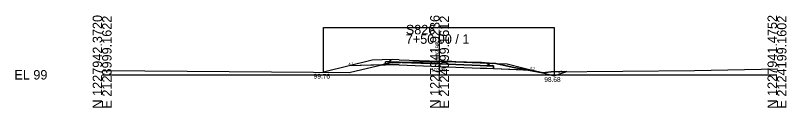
# Model space of a CAD drawing. Extents: x 2118382 to 2118616, y 1213030 to 1222057.
# Drawn here: x 2118381.9 to 2118610.4, y 1218030.1 to 1218057.3 of the extents above; entities that cross this region are included whole.
import ezdxf

# ---------------------------------------------------------------- set-up
doc = ezdxf.new("R2010")
doc.units = 0
for name, color, linetype in [('XS_CELL', 7, 'Continuous'), ('XS_M_DITCH', 7, 'Continuous'), ('XS_M_SHAPES_EARTHWORK', 7, 'Continuous'), ('XS_P_FINISHED_GRADE', 7, 'Continuous'), ('XS_P_FINISHED_GRADE_ELEV_TX', 7, 'Continuous'), ('XS_P_SUBGRADE_GRANULAR', 7, 'Continuous'), ('XS_P_SUBGRADE_PAVEMENT', 7, 'Continuous'), ('XS_P_TX_DCH', 7, 'Continuous'), ('XS_P_TX_FS_BS', 7, 'Continuous'), ('XS_X_GROUND', 7, 'Continuous'), ('XS_X_GROUND_TX', 7, 'Continuous')]:
    doc.layers.add(name, color=color, linetype=linetype)

msp = doc.modelspace()

# ---------------------------------------------------------------- linework, layer by layer
at = {"layer": 'XS_CELL'}
for p, q in [((2118507.6, 1218039.8), (2118507.6, 1218051.76)), ((2118407.6, 1218039.8), (2118507.6, 1218039.8)), ((2118507.6, 1218039.8), (2118607.6, 1218039.8))]:
    msp.add_line(p, q, dxfattribs=at)
at = {"layer": 'XS_M_DITCH'}
for p, q in [((2118473.2, 1218040.56), (2118473.2, 1218053.78)), ((2118473.2, 1218053.78), (2118541.6, 1218053.78)), ((2118541.6, 1218053.78), (2118541.6, 1218039.49))]:
    msp.add_line(p, q, dxfattribs=at)
at = {"layer": 'XS_M_SHAPES_EARTHWORK'}
for p, q in [((2118480.78, 1218042.45), (2118473.2, 1218040.56)), ((2118490.47, 1218042.74), (2118480.78, 1218042.45)), ((2118487.88, 1218042.15), (2118490.47, 1218042.74)), ((2118491.6, 1218043.01), (2118490.47, 1218042.74)), ((2118490.47, 1218042.74), (2118491.6, 1218042.78)), ((2118493.41, 1218043.43), (2118491.6, 1218043.01)), ((2118491.6, 1218043.01), (2118491.6, 1218042.78)), ((2118491.6, 1218042.78), (2118491.6, 1218043.01)), ((2118491.6, 1218042.78), (2118493.6, 1218042.84)), ((2118493.8, 1218043.44), (2118493.41, 1218043.43)), ((2118493.6, 1218042.84), (2118495.6, 1218042.76)), ((2118496.05, 1218043.46), (2118493.8, 1218043.44)), ((2118495.6, 1218042.76), (2118507.6, 1218042.28)), ((2118496.49, 1218043.47), (2118496.05, 1218043.46)), ((2118506.07, 1218043.74), (2118496.49, 1218043.47)), ((2118496.49, 1218043.47), (2118507.6, 1218043.03)), ((2118507.6, 1218043.03), (2118496.49, 1218043.47)), ((2118507.6, 1218043.78), (2118506.07, 1218043.74)), ((2118511.24, 1218043.68), (2118507.6, 1218043.78)), ((2118507.6, 1218043.78), (2118519.6, 1218043.3)), ((2118519.6, 1218043.3), (2118507.6, 1218043.78)), ((2118507.6, 1218043.03), (2118519.6, 1218042.55)), ((2118519.6, 1218042.55), (2118507.6, 1218043.03)), ((2118507.6, 1218042.28), (2118519.6, 1218041.8)), ((2118512.16, 1218043.65), (2118511.24, 1218043.68)), ((2118519.08, 1218043.44), (2118512.16, 1218043.65)), ((2118520.05, 1218043.39), (2118519.08, 1218043.44)), ((2118519.6, 1218043.3), (2118521.6, 1218043.23)), ((2118521.6, 1218043.23), (2118519.6, 1218043.3)), ((2118519.6, 1218042.55), (2118521.6, 1218042.48)), ((2118521.6, 1218042.48), (2118519.6, 1218042.55)), ((2118523.35, 1218043.16), (2118520.05, 1218043.39)), ((2118521.6, 1218043.23), (2118522.28, 1218042.74)), ((2118523.35, 1218043.16), (2118521.6, 1218043.23)), ((2118521.6, 1218043.23), (2118523.35, 1218043.16)), ((2118522.28, 1218042.74), (2118521.6, 1218043.23)), ((2118521.6, 1218042.48), (2118522.45, 1218042.44)), ((2118522.45, 1218042.44), (2118521.6, 1218042.48)), ((2118522.28, 1218042.74), (2118522.45, 1218042.44)), ((2118522.45, 1218042.44), (2118522.28, 1218042.74)), ((2118522.45, 1218042.44), (2118523.6, 1218042.4)), ((2118523.6, 1218042.4), (2118522.45, 1218042.44)), ((2118524.3, 1218043.09), (2118523.35, 1218043.16)), ((2118523.6, 1218042.4), (2118523.6, 1218041.65)), ((2118523.6, 1218041.65), (2118523.6, 1218042.4)), ((2118529.16, 1218042.09), (2118524.3, 1218043.09)), ((2118473.2, 1218040.56), (2118480.83, 1218040.5)), ((2118480.83, 1218040.5), (2118487.88, 1218042.15)), ((2118519.6, 1218041.8), (2118521.6, 1218041.73)), ((2118521.6, 1218041.73), (2118523.6, 1218041.65)), ((2118523.6, 1218041.65), (2118533.4, 1218041.25)), ((2118533.4, 1218041.25), (2118529.16, 1218042.09)), ((2118534.75, 1218041.2), (2118533.4, 1218041.25)), ((2118533.4, 1218041.25), (2118538.07, 1218040.33)), ((2118538.18, 1218040.34), (2118534.75, 1218041.2)), ((2118538.07, 1218040.33), (2118538.18, 1218040.34)), ((2118540.63, 1218040.69), (2118538.18, 1218040.34)), ((2118538.18, 1218040.34), (2118541.6, 1218039.49)), ((2118545.36, 1218040.74), (2118540.63, 1218040.69)), ((2118541.6, 1218039.49), (2118545.36, 1218040.74))]:
    msp.add_line(p, q, dxfattribs=at)
at = {"layer": 'XS_P_FINISHED_GRADE'}
for p, q in [((2118487.6, 1218044.16), (2118473.2, 1218040.56)), ((2118493.6, 1218044.34), (2118487.6, 1218044.16)), ((2118495.6, 1218044.26), (2118493.6, 1218044.34)), ((2118495.6, 1218044.26), (2118507.6, 1218043.78)), ((2118507.6, 1218043.78), (2118519.6, 1218043.3)), ((2118519.6, 1218043.3), (2118521.6, 1218043.23)), ((2118521.6, 1218043.23), (2118527.6, 1218042.99)), ((2118527.6, 1218042.99), (2118541.6, 1218039.49)), ((2118541.6, 1218039.49), (2118545.36, 1218040.74))]:
    msp.add_line(p, q, dxfattribs=at)
at = {"layer": 'XS_P_SUBGRADE_GRANULAR'}
for p, q in [((2118491.6, 1218042.78), (2118480.78, 1218042.45)), ((2118492.71, 1218043.62), (2118491.6, 1218043.59)), ((2118491.6, 1218042.78), (2118491.6, 1218043.59)), ((2118493.6, 1218042.84), (2118491.6, 1218042.78)), ((2118495.6, 1218042.76), (2118493.6, 1218042.84)), ((2118495.6, 1218042.76), (2118507.6, 1218042.28)), ((2118507.6, 1218042.28), (2118519.6, 1218041.8)), ((2118522.45, 1218042.44), (2118523.6, 1218042.4)), ((2118523.6, 1218041.65), (2118523.6, 1218042.4)), ((2118519.6, 1218041.8), (2118521.6, 1218041.73)), ((2118521.6, 1218041.73), (2118523.6, 1218041.65)), ((2118523.6, 1218041.65), (2118534.75, 1218041.2))]:
    msp.add_line(p, q, dxfattribs=at)
at = {"layer": 'XS_P_SUBGRADE_PAVEMENT'}
for p, q in [((2118492.88, 1218043.91), (2118492.71, 1218043.62)), ((2118495.6, 1218043.51), (2118492.71, 1218043.62)), ((2118493.6, 1218044.34), (2118492.88, 1218043.91)), ((2118495.6, 1218043.51), (2118507.6, 1218043.03)), ((2118507.6, 1218043.03), (2118519.6, 1218042.55)), ((2118519.6, 1218042.55), (2118521.6, 1218042.48)), ((2118521.6, 1218043.23), (2118522.28, 1218042.74)), ((2118521.6, 1218042.48), (2118522.45, 1218042.44)), ((2118522.28, 1218042.74), (2118522.45, 1218042.44))]:
    msp.add_line(p, q, dxfattribs=at)
at = {"layer": 'XS_X_GROUND'}
for p, q in [((2118487.88, 1218042.15), (2118493.41, 1218043.43)), ((2118493.41, 1218043.43), (2118493.8, 1218043.44)), ((2118493.8, 1218043.44), (2118496.05, 1218043.46)), ((2118496.05, 1218043.46), (2118506.07, 1218043.74)), ((2118506.07, 1218043.74), (2118507.6, 1218043.78)), ((2118507.6, 1218043.78), (2118511.24, 1218043.68)), ((2118511.24, 1218043.68), (2118512.16, 1218043.65)), ((2118512.16, 1218043.65), (2118519.08, 1218043.44)), ((2118519.08, 1218043.44), (2118520.05, 1218043.39)), ((2118520.05, 1218043.39), (2118524.3, 1218043.09)), ((2118524.3, 1218043.09), (2118529.16, 1218042.09)), ((2118407.84, 1218041.1), (2118470.25, 1218040.58)), ((2118470.25, 1218040.58), (2118480.83, 1218040.5)), ((2118480.83, 1218040.5), (2118487.88, 1218042.15)), ((2118529.16, 1218042.09), (2118538.07, 1218040.33)), ((2118538.07, 1218040.33), (2118540.63, 1218040.69)), ((2118540.63, 1218040.69), (2118583.19, 1218041.11)), ((2118583.19, 1218041.11), (2118607.84, 1218041.54))]:
    msp.add_line(p, q, dxfattribs=at)

# ---------------------------------------------------------------- texts
at = {"layer": 'XS_CELL'}
for s, p in [('N 1227942.3720', (2118407.6, 1218029.8)), ('E 2123999.1622', (2118410.4, 1218029.8)), ('N 1227941.9236', (2118507.6, 1218029.8)), ('E 2124099.1612', (2118510.4, 1218029.8)), ('N 1227941.4752', (2118607.6, 1218029.8)), ('E 2124199.1602', (2118610.4, 1218029.8))]:
    msp.add_text(s, height=2.8, rotation=90, dxfattribs=at).set_placement(p)
for s, p in [('S826', (2118497.6, 1218051.76)), ('7+50.00 / 1', (2118497.6, 1218048.96)), ('EL 99', (2118381.6, 1218038.4))]:
    msp.add_text(s, height=2.8, dxfattribs=at).set_placement(p)
at = {"layer": 'XS_P_FINISHED_GRADE_ELEV_TX'}
msp.add_text(' 102.98', height=1.25, rotation=90, dxfattribs=at).set_placement((2118507.6, 1218043.78))
at = {"layer": 'XS_P_TX_DCH'}
for s, p in [('99.76', (2118470.31, 1218038.68)), ('98.68', (2118538.64, 1218037.7))]:
    msp.add_text(s, height=1.4, dxfattribs=at).set_placement(p)
at = {"layer": 'XS_P_TX_FS_BS'}
for s, rotation, p in [('4:1', 14.0362, (2118480.69, 1218042.52)), ('4:1', 345.9638, (2118534.3, 1218041.53)), ('3:1', 18.4349, (2118542.76, 1218040))]:
    msp.add_text(s, height=0.8, rotation=rotation, dxfattribs=at).set_placement(p)
at = {"layer": 'XS_X_GROUND_TX'}
msp.add_text('102.98', height=1, dxfattribs=at).set_placement((2118505.2, 1218040.79))

doc.saveas('drawing.dxf')
